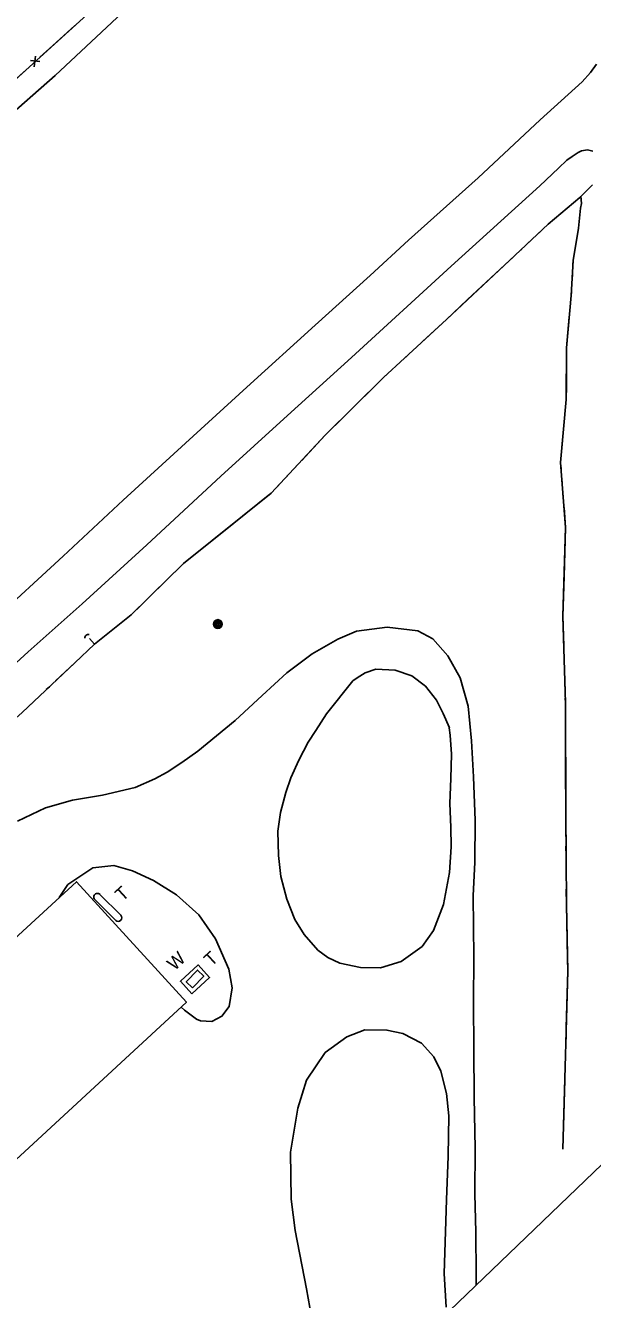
# Model space of a CAD drawing. Extents: x 295302 to 297577, y 27143 to 29590.
# Drawn here: x 296036 to 296296, y 27998 to 28582 of the extents above; entities that cross this region are included whole.
import ezdxf

# ---------------------------------------------------------------- set-up
doc = ezdxf.new("R2010")
doc.units = 0
for name, color, linetype in [('Level 11', 7, 'Continuous'), ('Level 12', 7, 'Continuous'), ('Level 14', 7, 'Continuous'), ('Level 15', 7, 'Continuous'), ('Level 17', 7, 'Continuous'), ('Level 19', 7, 'Continuous'), ('Level 4', 7, 'Continuous')]:
    doc.layers.add(name, color=color, linetype=linetype)

msp = doc.modelspace()

# ---------------------------------------------------------------- linework, layer by layer
at = {"layer": 'Level 11'}
for points in [[(295875.36, 28176.97), (295933.16, 28229.89), (295963.95, 28257.42), (295994.85, 28284.91), (296020.17, 28308.14), (296053.31, 28338.3), (296080.66, 28364.03), (296109.33, 28390.19), (296137.45, 28415.82), (296168.64, 28444.28), (296193.89, 28466.94), (296211.46, 28483.1), (296243.37, 28511.75), (296271.82, 28538.33), (296291, 28555.78), (296294.87, 28559.97), (296297.65, 28563.85)], [(295889.55, 28159.05), (295929.9, 28196.61), (295960.23, 28223.99), (295994.84, 28255.85), (296037.19, 28294.52), (296061.88, 28316.46), (296091.53, 28343.54), (296125.49, 28375.06), (296156.05, 28402.79), (296185.39, 28429.34), (296231.09, 28471.28), (296271.66, 28507.98), (296280.16, 28516.21), (296284, 28519.76), (296286.47, 28521.53), (296289.27, 28523.36), (296290.75, 28524.15), (296293.46, 28524.51), (296295.97, 28523.95)]]:
    msp.add_lwpolyline(points, dxfattribs=at)
at = {"layer": 'Level 12'}
for p, q in [((296077.32, 28171.48), (296067.78, 28181.02)), ((296070.11, 28183.36), (296079.66, 28173.81))]:
    msp.add_line(p, q, dxfattribs=at)
msp.add_lwpolyline([(295997.3, 28030.32), (296109.73, 28134.03), (296059.4, 28189.22), (295949.16, 28088.06)], dxfattribs=at)
msp.add_lwpolyline([(296112.48, 28140.58), (296117.66, 28145.92), (296114.8, 28148.71), (296109.61, 28143.37)], close=True, dxfattribs=at)
for centre, start, end in [((296068.91, 28182.23), 43.02238, 226.98046), ((296078.45, 28172.69), 227.11431, 42.85382)]:
    msp.add_arc(centre, 1.65, start, end, dxfattribs=at)
at = {"layer": 'Level 14'}
for centre, radius in [((296124.12, 28307.26), 2.02), ((296124.11, 28307.27), 1.52), ((296124.14, 28307.24), 1.01), ((296124.13, 28307.25), 0.502)]:
    msp.add_circle(centre, radius, dxfattribs=at)
at = {"layer": 'Level 15'}
for p, q in [((296042.61, 28564.96), (296038.34, 28565.44)), ((296040.53, 28567.51), (296039.94, 28562.53))]:
    msp.add_line(p, q, dxfattribs=at)
for points in [[(296276.18, 28846.07), (296285.34, 28791.28), (296208.62, 28719.5), (296139.52, 28656.15), (296075.6, 28596.91), (296001.45, 28529.71), (295938.47, 28471.89), (295884.83, 28422.36), (295819.8, 28364.6), (295769.53, 28318.85), (295750.14, 28301.92), (295710.44, 28274.72)], [(296058.61, 28581.51), (296050.08, 28573.79)], [(296050.08, 28573.79), (296042.59, 28566.99)], [(296037.63, 28562.5), (296029.11, 28554.78)]]:
    msp.add_lwpolyline(points, dxfattribs=at)
msp.add_lwpolyline([(296112.17, 28137.85), (296120.36, 28145.31), (296115.12, 28151.06), (296106.93, 28143.6)], close=True, dxfattribs=at)
msp.add_arc((296064.8, 28300.89), 1.61, 77.70064, 183.94021, dxfattribs=at)
at = {"layer": 'Level 17'}
for points in [[(295769.8, 28306.78), (295832.14, 28364.62), (295878.58, 28406.02), (295925.45, 28449.27), (295976.52, 28494.41), (296049.61, 28558.68), (296125.2, 28629.4), (296196.94, 28696.67), (296248.89, 28742.92), (296276.75, 28769.94), (296287.3, 28777.73)], [(296032.34, 28216.99), (296045.11, 28223.03), (296057.56, 28226.56), (296071.26, 28228.88), (296086.2, 28232.38), (296095.23, 28236.38), (296100.86, 28239.33), (296107.61, 28243.76), (296114.95, 28249.06), (296132.02, 28263.13), (296144.46, 28274.48), (296155.68, 28284.86), (296167.4, 28293.56), (296179.02, 28300.35), (296187.63, 28303.95), (296201.7, 28305.88), (296215.77, 28304.11), (296222.61, 28300.45), (296229.47, 28292.71), (296235.08, 28282.68), (296238.82, 28269.63), (296240.35, 28253.77), (296241.21, 28237.31), (296242.04, 28217.28), (296241.92, 28198.18), (296241.11, 28182.69), (296241.35, 28154.71), (296241.28, 28133.94), (296241.42, 28112.45), (296241.53, 28090.4), (296241.97, 28066.95), (296241.8, 28046.15), (296242.37, 28028.64), (296242.41, 28009.16), (296242.46, 28004.32)], [(296230.19, 28259.76), (296227.38, 28266.32), (296224.29, 28272.34), (296219.19, 28278.74), (296213.02, 28283.47), (296205.37, 28286.19), (296196.47, 28286.61), (296191.66, 28284.98), (296187.98, 28282.67), (296186.04, 28281.19), (296173.89, 28266.14)], [(296173.89, 28266.14), (296168.96, 28258.52), (296165.56, 28253.08), (296161.29, 28244.97), (296157.56, 28236.77), (296155.27, 28230.02), (296152.78, 28220.94), (296151.53, 28212.35), (296151.84, 28201.2), (296152.91, 28191.62), (296155.72, 28181.28), (296159.4, 28171.87), (296163.69, 28165.02), (296169.99, 28157.89), (296174.46, 28154.53), (296180.03, 28151.91), (296189.53, 28149.91), (296198.68, 28149.79), (296208.05, 28152.58), (296217.8, 28159.53), (296222.91, 28166.82), (296227.54, 28178.79), (296230.23, 28193.41), (296231.07, 28205.13), (296230.8, 28214.24), (296230.45, 28225.07), (296230.83, 28236.46), (296231.24, 28247.63), (296230.64, 28256.34), (296230.18, 28259.78)], [(296051.47, 28181.94), (296055.3, 28187.93), (296066.76, 28195.59), (296076.45, 28196.71), (296085.02, 28194.17), (296094.66, 28189.77), (296105.14, 28183.22), (296115.44, 28173.98), (296123.06, 28163.04), (296129.08, 28149.18), (296130.62, 28140.53), (296129.3, 28132), (296126.01, 28127.53), (296121.43, 28125.22), (296116.19, 28125.48), (296114.28, 28126.29), (296111.88, 28128.04), (296108.8, 28130.38), (296107.24, 28131.73)], [(296228.71, 27994.32), (296227.89, 28009.72), (296228.44, 28028.96), (296228.83, 28043.51), (296229.68, 28063.47), (296229.96, 28081.92), (296228.94, 28092.22), (296226.33, 28102.37), (296223.13, 28109.01), (296217.5, 28115.24), (296208.9, 28119.61), (296201.61, 28121.25), (296191.46, 28121.3), (296183.23, 28118.12), (296173.33, 28110.96), (296164.72, 28098.35), (296160.83, 28085.47), (296157.33, 28065.22), (296157.66, 28043.82), (296159.6, 28029.34), (296164.7, 28002.71), (296168.58, 27981.31)]]:
    msp.add_lwpolyline(points, dxfattribs=at)
at = {"layer": 'Level 19'}
for points in [[(296067.61, 28298.02), (296084.4, 28311.53), (296108.33, 28335), (296148.5, 28367.18), (296173.26, 28393.74), (296200.07, 28420.25), (296228.82, 28446.85), (296257.69, 28473.78), (296275.51, 28490.47), (296289.91, 28502.78), (296293.53, 28506.28), (296295.72, 28508.47)], [(296274.73, 28489.73), (296275.51, 28490.47), (296289.91, 28502.78), (296293.53, 28506.28), (296295.72, 28508.47)], [(296282.15, 28066.74), (296283.43, 28109.79), (296284.53, 28148.26), (296283.81, 28178.8), (296283.5, 28221.52), (296283.4, 28271.12), (296282.21, 28310.81), (296283.43, 28351.46), (296281.15, 28381.26), (296283.76, 28410.17), (296283.94, 28433.82), (296286.03, 28457.76), (296286.97, 28473.79), (296289.39, 28488.73), (296290.3, 28497.76), (296290.72, 28499.94), (296290.42, 28503.27)], [(296286.85, 28471.88), (296286.97, 28473.79), (296289.39, 28488.73), (296290.3, 28497.76), (296290.72, 28499.94), (296290.42, 28503.27)], [(296270.47, 28485.75), (296271.89, 28487.07)], [(296266.22, 28481.76), (296267.64, 28483.09)], [(296261.97, 28477.78), (296263.39, 28479.11)], [(296238.55, 28455.92), (296257.69, 28473.78), (296259.13, 28475.13)], [(296286.47, 28465.33), (296286.6, 28467.51)], [(296286.09, 28458.78), (296286.21, 28460.97)], [(296217.92, 28436.76), (296228.82, 28446.85), (296238.55, 28455.92)], [(296285.55, 28452.25), (296285.73, 28454.43)], [(296283.81, 28416.24), (296283.94, 28433.82), (296285.17, 28447.89)], [(296209.36, 28428.85), (296210.79, 28430.16)], [(296213.64, 28432.8), (296215.07, 28434.12)], [(296205.09, 28424.89), (296206.51, 28426.21)], [(296182.15, 28402.53), (296200.07, 28420.25), (296202.23, 28422.25)], [(296281.45, 28384.65), (296283.76, 28410.17), (296283.81, 28416.24)], [(296162.58, 28382.28), (296173.26, 28393.74), (296182.15, 28402.53)], [(296158.61, 28378.02), (296159.93, 28379.44)], [(296281.39, 28378.11), (296281.22, 28380.29)], [(296150.66, 28369.5), (296151.99, 28370.92)], [(296154.64, 28373.76), (296155.96, 28375.18)], [(296281.89, 28371.57), (296281.72, 28373.75)], [(296125.97, 28349.13), (296147.95, 28366.73)], [(296282.39, 28365.03), (296282.22, 28367.21)], [(296282.76, 28329.01), (296283.43, 28351.46), (296282.73, 28360.67)], [(296104.36, 28331.11), (296108.33, 28335), (296125.97, 28349.13)], [(296096.05, 28322.95), (296097.43, 28324.31)], [(296100.21, 28327.03), (296101.59, 28328.39)], [(296282.61, 28297.33), (296282.21, 28310.81), (296282.76, 28329.01)], [(296091.89, 28318.87), (296093.28, 28320.23)], [(296067.61, 28298.02), (296084.4, 28311.53), (296089.12, 28316.15)], [(295897.02, 28145.94), (295935.14, 28183.88), (295971, 28214.98), (296008.91, 28244.12), (296034.43, 28266.81), (296058.6, 28289.49), (296067.61, 28298.02), (296065.26, 28300.62)], [(296049.74, 28281.18), (296058.6, 28289.49), (296067.61, 28298.02), (296065.26, 28300.62)], [(296282.81, 28290.77), (296282.74, 28292.96)], [(296283.01, 28284.22), (296282.94, 28286.4)], [(296045.51, 28277.21), (296046.92, 28278.53)], [(296283.2, 28277.66), (296283.14, 28279.84)], [(296041.27, 28273.23), (296042.69, 28274.56)], [(296283.46, 28241.59), (296283.4, 28271.12), (296283.33, 28273.29)], [(296037.04, 28269.26), (296038.45, 28270.58)], [(296283.58, 28209.89), (296283.5, 28221.52), (296283.46, 28241.59)], [(296283.63, 28203.33), (296283.61, 28205.52)], [(296283.68, 28196.77), (296283.66, 28198.96)], [(296283.73, 28190.22), (296283.71, 28192.4)], [(296284.39, 28154.15), (296283.81, 28178.8), (296283.76, 28185.84)], [(296283.79, 28122.47), (296284.53, 28148.26), (296284.39, 28154.15)], [(296283.6, 28115.91), (296283.67, 28118.1)], [(296283.42, 28109.35), (296283.43, 28109.79), (296283.48, 28111.54)], [(296283.22, 28102.8), (296283.29, 28104.99)], [(296282.15, 28066.74), (296283.09, 28098.43)]]:
    msp.add_lwpolyline(points, dxfattribs=at)
at = {"layer": 'Level 4'}
msp.add_lwpolyline([(296117.92, 27884.67), (296866.66, 28604.06)], dxfattribs=at)

# ---------------------------------------------------------------- texts
at = {"layer": 'Level 12'}
for p in [(296080.42, 28179.89), (296121.16, 28150.06)]:
    msp.add_text('T', height=6, rotation=42.51596, dxfattribs=at).set_placement(p)
at = {"layer": 'Level 15'}
msp.add_text('W', height=6, rotation=42.51596, dxfattribs=at).set_placement((296104.23, 28148.16))

doc.saveas('drawing.dxf')
